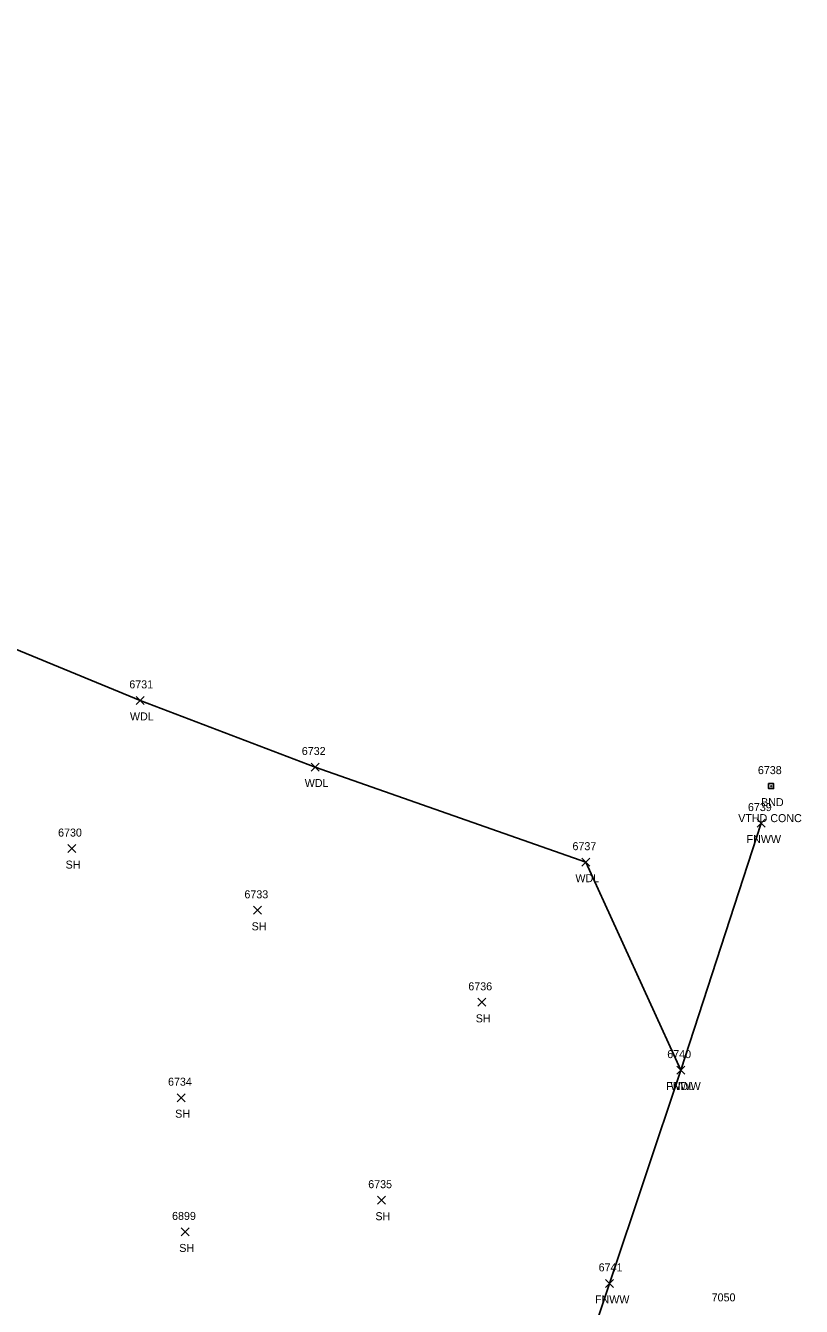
# Model space of a CAD drawing. Extents: x 1678863 to 1683592, y 407783 to 418211.
# Drawn here: x 1680837 to 1681031, y 409450.7 to 409770.8 of the extents above; entities that cross this region are included whole.
import ezdxf

# ---------------------------------------------------------------- set-up
doc = ezdxf.new("R2010")
doc.units = 0
for name, color, linetype in [('L_A', 7, 'Continuous'), ('L_I', 7, 'Continuous'), ('L_TIC', 7, 'Continuous'), ('LAWA', 7, 'Continuous'), ('Level 18', 7, 'Continuous'), ('LFNC', 7, 'Continuous'), ('M_A', 7, 'Continuous'), ('M_C', 7, 'Continuous'), ('M_I', 7, 'Continuous')]:
    doc.layers.add(name, color=color, linetype=linetype)

msp = doc.modelspace()

# ---------------------------------------------------------------- linework, layer by layer
at = {"layer": 'L_TIC'}
for points in [[(1680864.73, 409601.13), (1680866.73, 409603.13)], [(1680866.73, 409601.13), (1680864.73, 409603.13)], [(1680908.42, 409584.48), (1680910.42, 409586.48)], [(1680910.42, 409584.48), (1680908.42, 409586.48)], [(1681019.97, 409570.46), (1681021.97, 409572.46)], [(1681021.97, 409570.46), (1681019.97, 409572.46)], [(1680847.57, 409564.09), (1680849.57, 409566.09)], [(1680849.57, 409564.09), (1680847.57, 409566.09)], [(1680976.1, 409560.69), (1680978.1, 409562.69)], [(1680978.1, 409560.69), (1680976.1, 409562.69)], [(1680894.07, 409548.66), (1680896.07, 409550.66)], [(1680896.07, 409548.66), (1680894.07, 409550.66)], [(1680950.11, 409525.66), (1680952.11, 409527.66)], [(1680952.11, 409525.66), (1680950.11, 409527.66)], [(1680999.88, 409508.71), (1681001.88, 409510.71)], [(1681001.88, 409508.71), (1680999.88, 409510.71)], [(1680999.88, 409508.71), (1681001.88, 409510.71)], [(1681001.88, 409508.71), (1680999.88, 409510.71)], [(1680874.97, 409501.82), (1680876.97, 409503.82)], [(1680876.97, 409501.82), (1680874.97, 409503.82)], [(1680925.03, 409476.2), (1680927.03, 409478.2)], [(1680927.03, 409476.2), (1680925.03, 409478.2)], [(1680875.98, 409468.27), (1680877.98, 409470.27)], [(1680877.98, 409468.27), (1680875.98, 409470.27)], [(1680982.07, 409455.41), (1680984.07, 409457.41)], [(1680984.07, 409455.41), (1680982.07, 409457.41)]]:
    msp.add_lwpolyline(points, dxfattribs=at)
at = {"layer": 'LAWA'}
msp.add_lwpolyline([(1680349.85, 409770.79), (1680397.53, 409750.97), (1680442.31, 409734.11), (1680494.41, 409720.8), (1680527.33, 409708.46), (1680567.84, 409695.13), (1680606.41, 409684.25), (1680660.58, 409669.09), (1680715.74, 409654.2), (1680757.96, 409641.31), (1680807.22, 409626.15), (1680865.73, 409602.13), (1680909.42, 409585.48), (1680977.1, 409561.69), (1681000.88, 409509.71)], dxfattribs=at)
at = {"layer": 'Level 18'}
msp.add_lwpolyline([(1681022.83, 409581.33), (1681024.08, 409581.33), (1681024.08, 409580.08), (1681022.83, 409580.08)], close=True, dxfattribs=at)
msp.add_circle((1681023.46, 409580.7), 0.0833, dxfattribs=at)
at = {"layer": 'LFNC'}
msp.add_lwpolyline([(1681020.97, 409571.46), (1681000.88, 409509.71), (1680983.07, 409456.41), (1680966.99, 409407.97), (1680949.18, 409354.43), (1680932.44, 409305.73), (1680912.74, 409247.22), (1680896.75, 409201.77), (1680883.78, 409168.4), (1680880.32, 409157.8), (1680862.92, 409120.89), (1680841.17, 409074.48), (1680829.25, 409048.23)], dxfattribs=at)

# ---------------------------------------------------------------- texts
at = {"layer": 'L_A'}
for s, p in [('WDL', (1680863.14, 409597.13)), ('WDL', (1680906.84, 409580.48)), ('FNWW', (1681017.32, 409566.46)), ('SH', (1680847.05, 409560.09)), ('WDL', (1680974.52, 409556.69)), ('SH', (1680893.56, 409544.66)), ('SH', (1680949.6, 409521.66)), ('FNWW', (1680997.23, 409504.71)), ('WDL', (1680998.3, 409504.71)), ('SH', (1680874.45, 409497.82)), ('SH', (1680924.52, 409472.2)), ('SH', (1680875.47, 409464.27)), ('FNWW', (1680979.41, 409451.41))]:
    msp.add_text(s, height=2, dxfattribs=at).set_placement(p)
at = {"layer": 'L_I'}
for s, p in [('6731', (1680862.98, 409605.13)), ('6732', (1680906.11, 409588.48)), ('6739', (1681017.66, 409574.46)), ('6730', (1680845.17, 409568.09)), ('6737', (1680973.79, 409564.69)), ('6733', (1680891.76, 409552.66)), ('6736', (1680947.75, 409529.66)), ('6740', (1680997.49, 409512.71)), ('6740', (1680997.49, 409512.71)), ('6734', (1680872.66, 409505.82)), ('6735', (1680922.72, 409480.2)), ('6899', (1680873.67, 409472.27)), ('6741', (1680980.33, 409459.41)), ('7050', (1681008.59, 409451.91))]:
    msp.add_text(s, height=2, dxfattribs=at).set_placement(p)
at = {"layer": 'M_A'}
msp.add_text('BND', height=2, dxfattribs=at).set_placement((1681020.95, 409575.7))
at = {"layer": 'M_C'}
msp.add_text('VTHD CONC', height=2, dxfattribs=at).set_placement((1681015.23, 409571.7))
at = {"layer": 'M_I'}
msp.add_text('6738', height=2, dxfattribs=at).set_placement((1681020.15, 409583.7))

doc.saveas('drawing.dxf')
